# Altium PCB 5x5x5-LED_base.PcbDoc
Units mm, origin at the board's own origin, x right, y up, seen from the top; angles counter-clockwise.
Board outline 97.2 x 97.2 mm, 2 copper layers (Top Layer, Bottom Layer); 46 components, 49 nets, 151 pads, 28 vias.
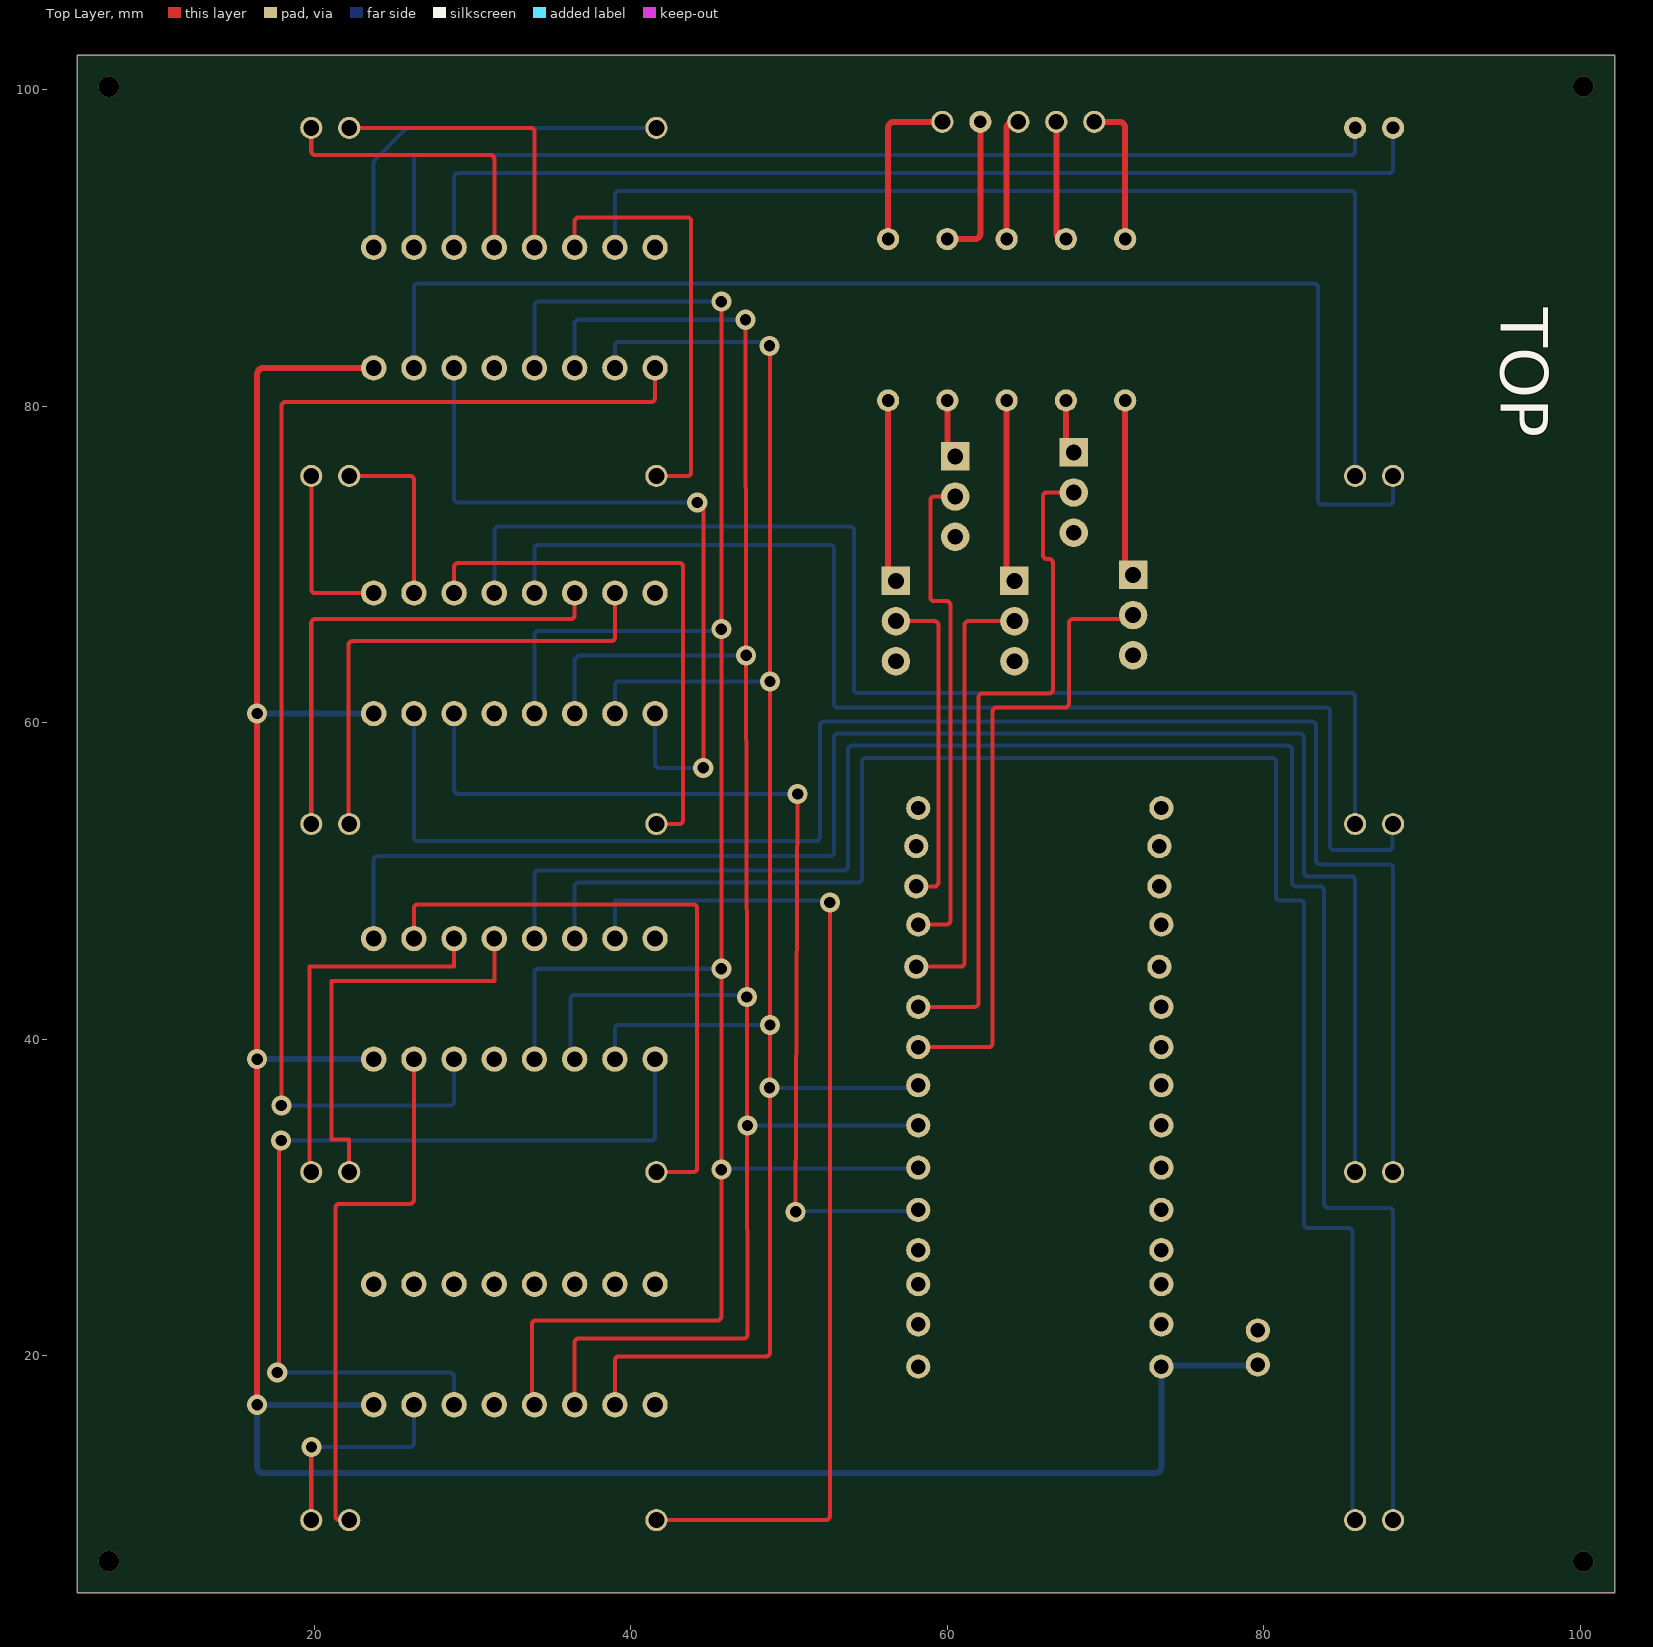
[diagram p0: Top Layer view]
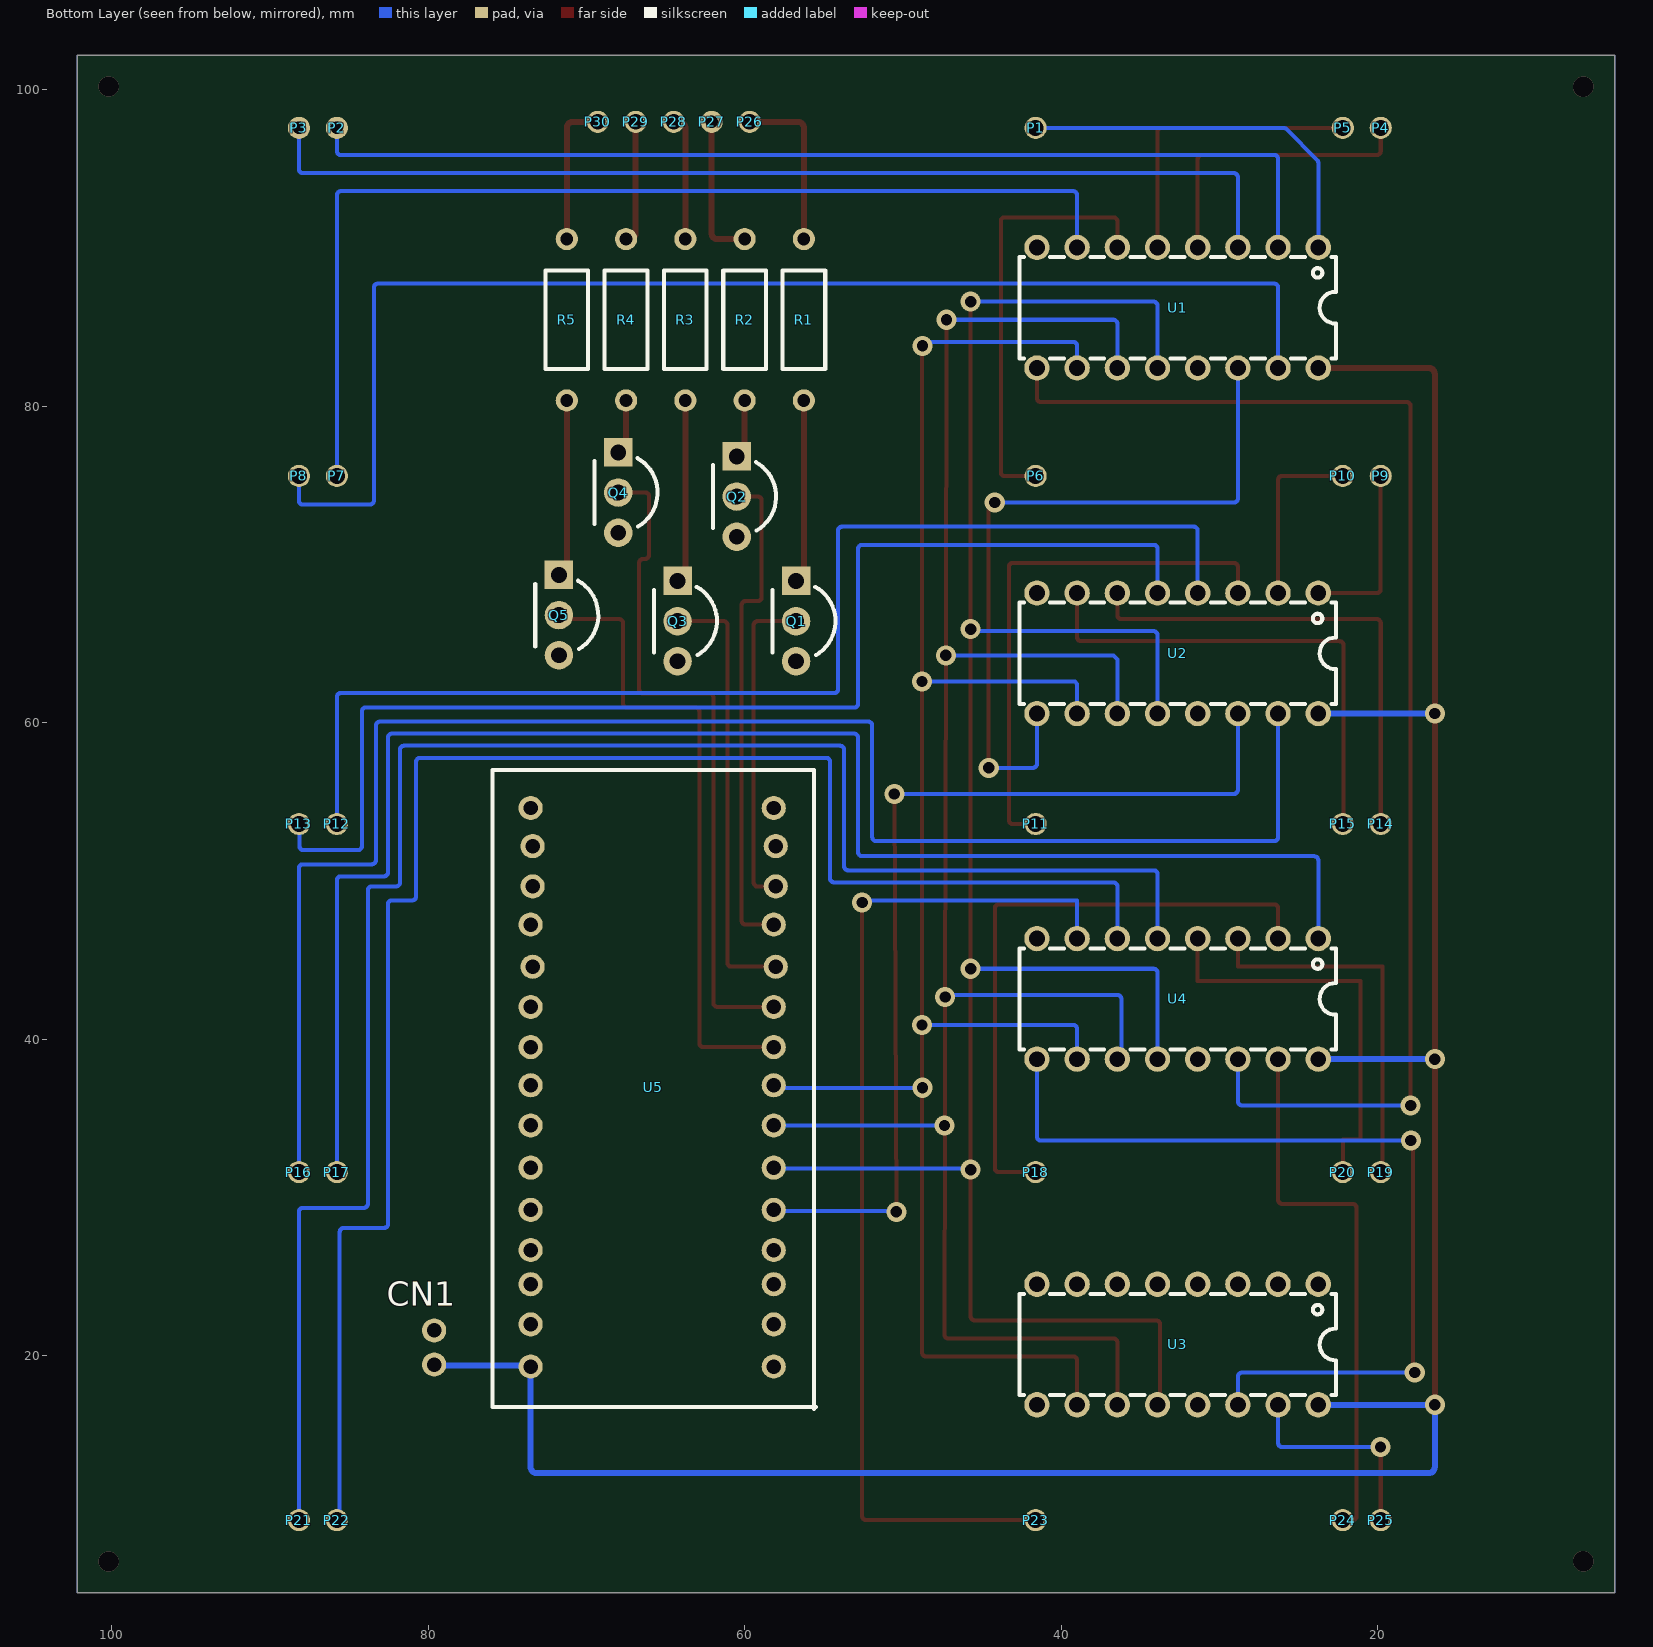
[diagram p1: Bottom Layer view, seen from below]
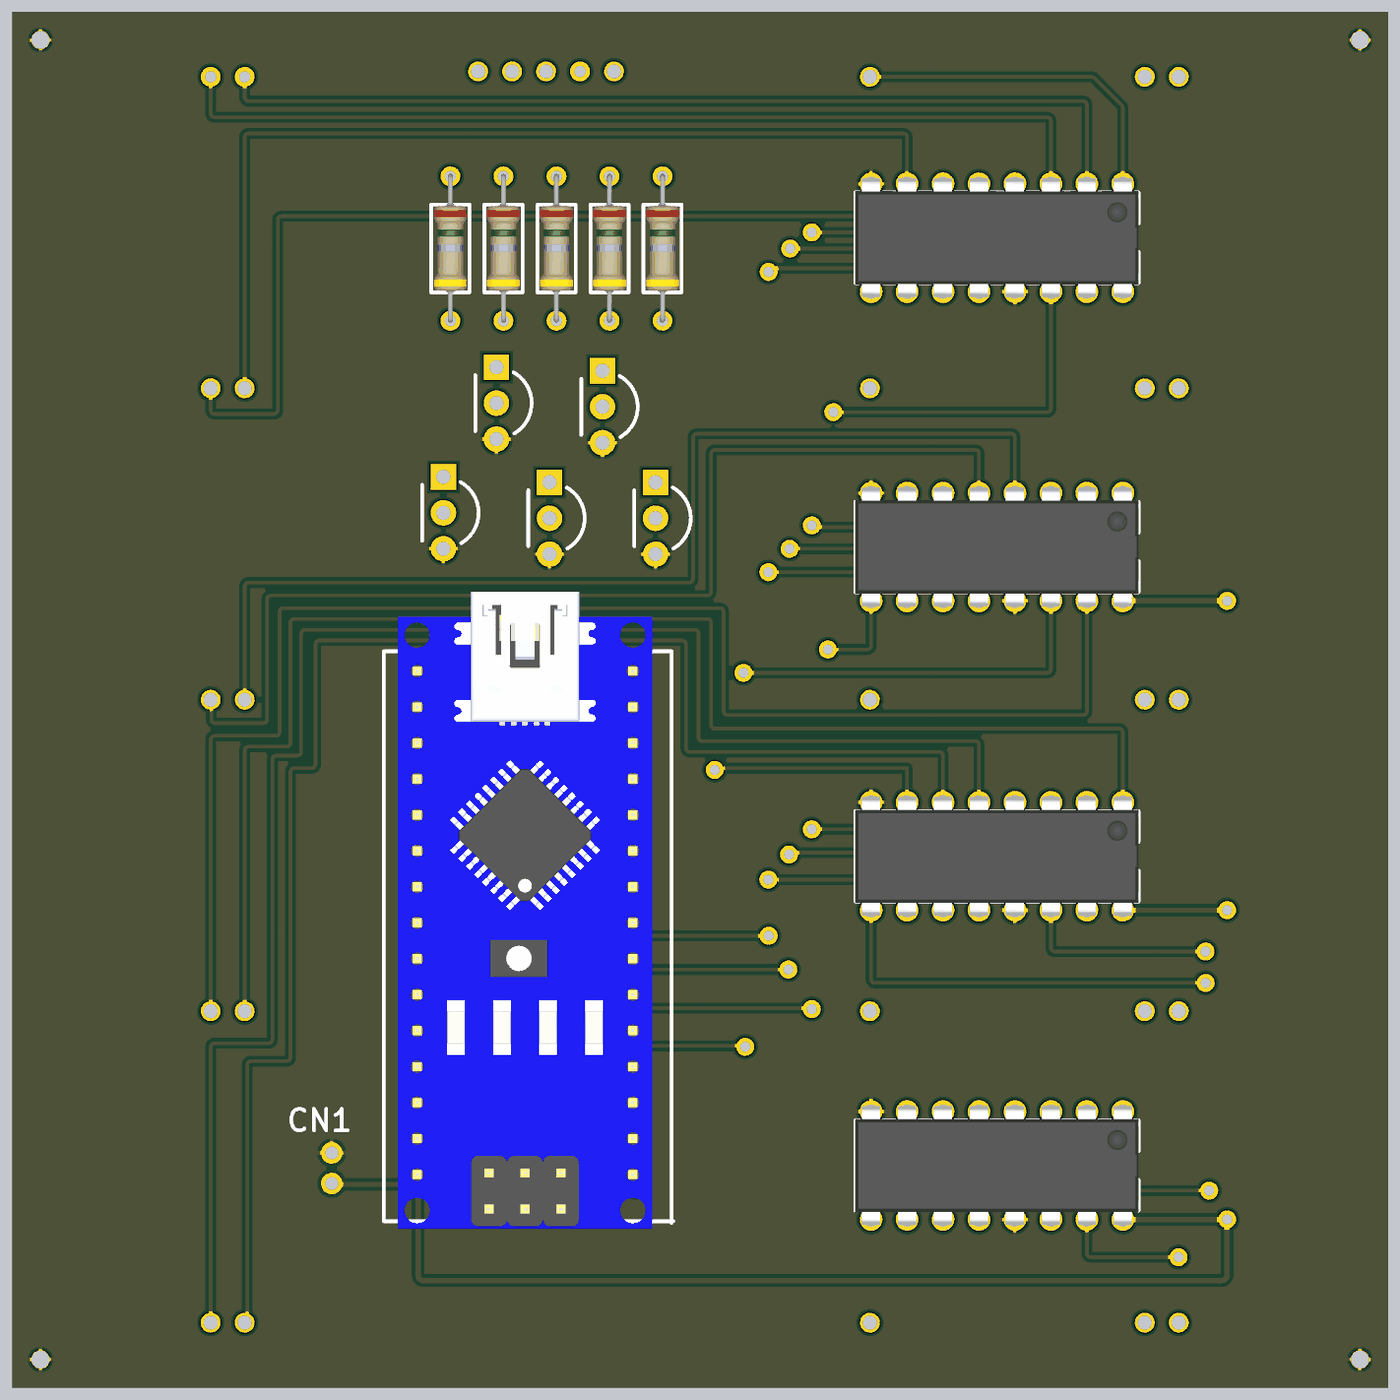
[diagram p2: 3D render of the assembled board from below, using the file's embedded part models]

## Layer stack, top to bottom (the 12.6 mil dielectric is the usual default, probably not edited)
Top Solder: solder mask 0.0102, Solder Resist, Dk 3.5
Top Layer: signal copper 0.0356
Dielectric 1: dielectric 0.32, FR-4, Dk 4.8
Bottom Layer: signal copper 0.0356
Bottom Solder: solder mask 0.0102, Solder Resist, Dk 3.5

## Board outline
5,5 102.198,5 102.198,102.198 5,102.198

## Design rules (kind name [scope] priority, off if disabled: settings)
Clearance [All] p1: gap=0.254 ignorepadtopadclearanceinfootprint=FALSE
PolygonConnect [All] p1: connectstyle=Relief reliefconductorwidth=0.254 reliefentries=4 polygonreliefangle="90 Angle" airgapwidth=0.254
RoutingVias [All] p1: holewidth=0.711 width=1.27 viastyle="Through Hole" minholewidth=0.711 minwidth=1.27 maxholewidth=0.711 maxwidth=1.27
SolderMaskExpansion [All] p1: expansion=0.102 istentingtop=FALSE
SupplyNets "Schematic Supply Nets_1" [InNet('GND')] p1: voltage=0.000
SupplyNets "Schematic Supply Nets" [InNet('+5')] p2: voltage=0.000
Width [All] p1: maxlimit=3 minlimit=0.254 preferedwidth=0.254 minimp=50.000000 maximp=50.000000 favimp=50.000000
30 further rules are at their usual default settings.

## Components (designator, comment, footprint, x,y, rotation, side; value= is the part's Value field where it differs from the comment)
CN1 "Power Connector" "POWER PORT" 79.629,19.431 r0 bottom
P1 "Port_1" port#1 41.613,93.599 r180 bottom
P2 "Port_1" port#2 85.777,93.599 r180 bottom
P3 "Port_1" port#2 88.177,93.599 r180 bottom
P4 "Port_1" port#1 19.799,93.599 r180 bottom
P5 "Port_1" port#1 22.199,93.599 r180 bottom
P6 "Port_1" port#3 41.613,72.599 r180 bottom
P7 "Port_1" port#3 85.777,72.599 r180 bottom
P8 "Port_1" port#3 88.177,72.599 r180 bottom
P9 "Port_1" port#3 19.799,72.599 r180 bottom
P10 "Port_1" port#4 22.2,72.599 r90 bottom
P11 "Port_1" port#5 41.613,51.599 r180 bottom
P12 "Port_1" port#6 85.778,51.599 r90 bottom
P13 "Port_1" port#6 88.178,51.599 r90 bottom
P14 "Port_1" port#6 19.8,51.599 r90 bottom
P15 "Port_1" port#6 22.2,51.599 r90 bottom
P16 "Port_1" port#7 88.178,30.599 r90 bottom
P17 "Port_1" port#7 85.778,30.599 r90 bottom
P18 "Port_1" port#7 41.614,30.599 r90 bottom
P19 "Port_1" port#7 19.8,30.599 r90 bottom
P20 "Port_1" port#7 22.2,30.599 r90 bottom
P21 "Port_1" port#8 88.177,9.599 r180 bottom
P22 "Port_1" port#8 85.778,9.599 r90 bottom
P23 "Port_1" port#8 41.614,9.599 r90 bottom
P24 "Port_1" port#8 22.2,9.599 r90 bottom
P25 "Port_1" port#8 19.8,9.599 r90 bottom
P26 "Port_1" port#9 59.69,93.98 r90 bottom locked
P27 "Port_1" port#10 62.09,93.98 r90 bottom locked
P28 "Port_1" port#9 64.49,93.98 r90 bottom locked
P29 "Port_1" port#9 66.89,93.98 r90 bottom locked
P30 "Port_1" port#9 69.29,93.98 r90 bottom locked
Q1 "BC547BTA" TO-92-3_L4.8-W3.7-P2.54-L 56.754,66.421 r270 bottom locked
Q2 "BC547BTA" TO-92-3_L4.8-W3.7-P2.54-L 60.501,74.295 r270 bottom locked
Q3 "BC547BTA" TO-92-3_L4.8-W3.7-P2.54-L 64.247,66.421 r270 bottom locked
Q4 "BC547BTA" TO-92-3_L4.8-W3.7-P2.54-L 67.994,74.549 r270 bottom locked
Q5 "BC547BTA" TO-92-3_L4.8-W3.7-P2.54-L 71.74,66.802 r270 bottom locked
R1 "1kΩ" RES-TH_BD2.7-L6.2-P10.20-D0.4 56.261,85.471 r270 bottom locked
R2 "1kΩ" RES-TH_BD2.7-L6.2-P10.20-D0.4 60.008,85.471 r270 bottom locked
R3 "1kΩ" RES-TH_BD2.7-L6.2-P10.20-D0.4 63.754,85.471 r270 bottom locked
R4 "1kΩ" RES-TH_BD2.7-L6.2-P10.20-D0.4 67.501,85.471 r270 bottom locked
R5 "1kΩ" RES-TH_BD2.7-L6.2-P10.20-D0.4 71.247,85.471 r270 bottom locked
U1 "74HC595N" DIP-16_L20.0-W6.4-P2.54-LS7.6-BL 32.639,86.233 r0 bottom locked
U2 "74HC595N" DIP-16_L20.0-W6.4-P2.54-LS7.6-BL 32.639,64.389 r0 bottom locked
U3 "74HC595N" DIP-16_L20.0-W6.4-P2.54-LS7.6-BL 32.639,20.701 r0 bottom locked
U4 "74HC595N" DIP-16_L20.0-W6.4-P2.54-LS7.6-BL 32.639,42.545 r0 bottom locked
U5 "ARDUINO_NANO" "ARDUINO NANO." 65.722,36.83 r0 bottom locked

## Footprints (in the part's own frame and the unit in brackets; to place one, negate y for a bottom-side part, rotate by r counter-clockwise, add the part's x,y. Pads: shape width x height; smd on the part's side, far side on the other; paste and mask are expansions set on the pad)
"ARDUINO NANO." [mil]
  round 60 hole 36 paste-99999 mask+2: 1(-297.5,690) 2(-297.5,585) 3(-297.5,485) 4(-297.5,400) 5(-297.5,300) 6(-297.5,195) 7(-297.5,90) 8(-297.5,-10) 9(-297.5,-105) 10(-297.5,-205) 11(-302.5,-305) 12(-297.5,-410) 13(-302.5,-505) 14(-302.5,-605) 15(-297.5,-700) 16(307.5,-700) 17(302.5,-605) 18(302.5,-505) 19(307.5,-410) 20(302.5,-305) 21(307.5,-205) 22(307.5,-105) 23(307.5,-10) 24(307.5,90) 25(307.5,195) 26(307.5,300) 27(307.5,400) 28(307.5,485) 29(307.5,585) 30(307.5,690)
  silkscreen extent -402,-795 402,795, body extent -344,-961 364,810, height 646
DIP-16_L20.0-W6.4-P2.54-LS7.6-BL [mm]
  round 1.6 hole 1: 1(-8.89,-3.81) 2(-6.35,-3.81) 3(-3.81,-3.81) 4(-1.27,-3.81) 5(1.27,-3.81) 6(3.81,-3.81) 7(6.35,-3.81) 8(8.89,-3.81) 9(8.89,3.81) 10(6.35,3.81) 11(3.81,3.81) 12(1.27,3.81) 13(-1.27,3.81) 14(-3.81,3.81) 15(-6.35,3.81) 16(-8.89,3.81)
  silkscreen extent -10,-3.2 10,3.2, body extent -10.02,-4.57 10.02,4.57, height 4.14
port#1 [mm]
  round 1.4 hole 1 copper offset 0,0: 1(0,4)
port#2 [mm]
  round 1.4 hole 0.8 copper offset 0,0: 1(0,4)
port#3 [mm]
  round 1.4 hole 1 copper offset 0,0: 1(0,3)
port#4 [mm]
  round 1.4 hole 1 copper offset 0,0: 1(3,0)
port#5 [mm]
  round 1.4 hole 1 copper offset 0,0: 1(0,2)
port#6 [mm]
  round 1.4 hole 1 copper offset 0,0: 1(2,0)
port#7 [mm]
  round 1.4 hole 1 copper offset 0,0: 1(1,0)
port#8 [mm]
  round 1.4 hole 1 copper offset 0,0: 1(0,0)
port#9 [mm]
  round 1.4 hole 1 copper offset 0,0: 1(4,0)
port#10 [mm]
  round 1.4 hole 0.8 copper offset 0,0: 1(4,0)
"POWER PORT" [mil]
  round 60 hole 36 paste-99999 mask+2: 1(0,0) 2(0,-85)
RES-TH_BD2.7-L6.2-P10.20-D0.4 [mm]
  round 1.4 hole 0.8 copper offset 0,0: 1(-5.1,0) 2(5.1,0)
  silkscreen extent -3.1,-1.35 3.1,1.35, body extent -5.27,-1.15 5.24,1.15, height 2.51
TO-92-3_L4.8-W3.7-P2.54-L [mm]
  rect 1.8x1.8 hole 1: 1(-2.54,0)
  round 1.8 hole 1: 2(0,0) 3(2.54,0)
  silkscreen extent -2.17,-1.5 2.14,2.48

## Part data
Q1 Q2 Q3 Q4 Q5: Collector Cut-Off Current (Icbo)=15nA, Collector-Emitter Saturation Voltage (VCE(sat)@Ic,Ib)=90mV@10mA,0.5mA, DC Current Gain (hFE@Ic,Vce)=110@2mA,5V, JLCPCB Part Class="Extended Part", LCSC Part Name="NPN 电流:100mA 耐压:45V", Manufacturer=onsemi(安森美), Operating Temperature=-65℃~+150℃, Transition Frequency (fT)=300MHz
R1 R2 R3 R4 R5: library part MF1/4W-1K±1%-ST52, JLCPCB Part Class="Extended Part", LCSC Part Name="金属膜电阻 1kΩ ±1% 250mW", Manufacturer=VO(翔胜), Operating Temperature Range=-55℃~+155℃, Overload Voltage (Max)=250V, Power(Watts)=250mW, Temperature Coefficient=±100ppm/℃, Tolerance=±1%
U1 U2 U3 U4: library part 74HC595N_C507175, JLCPCB Part Class="Extended Part", LCSC Part Name="具有三态输出寄存器的 8 位移位寄存器", Manufacturer=HGSEMI(华冠)

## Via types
v1: diameter 1.27, hole 0.711, Top Layer to Bottom Layer, 24 vias
v2: diameter 1.27, hole 1.27, Top Layer to Bottom Layer, 4 vias

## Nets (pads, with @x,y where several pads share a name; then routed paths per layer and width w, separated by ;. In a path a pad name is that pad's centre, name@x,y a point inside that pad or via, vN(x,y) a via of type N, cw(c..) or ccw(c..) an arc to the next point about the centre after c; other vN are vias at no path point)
+5: CN1.1 U1.16 U2.16 U3.16 U4.16 U5.30 | length 168.8
  Top Layer w0.381: v1(16.383,16.891) v1(16.383,38.735) v1(16.383,60.579) 16.383,82.042 cw(c16.764,82.042) 16.764,82.423 U1.16 ; CN1.1@79.566,19.367 CN1.1
  Bottom Layer w0.381: v1(16.383,38.735) U4.16 ; v1(16.383,60.579) U2.16 ; U3.16 v1(16.383,16.891) 16.383,12.952 ccw(c16.764,12.954) 16.764,12.573 73.152,12.573 ccw(c73.152,12.954) 73.533,12.954 U5.30 ; U5.30@73.596,19.367 CN1.1@79.566,19.367
CLOCK_PIN: U1.12 U2.12 U3.12 U4.12 U5.6 | length 144
  Top Layer w0.254: U3.12 33.829,16.971 cw(c34.009,17.151) 33.755,17.151 33.755,21.971 cw(c34.009,21.971) 34.009,22.225 45.466,22.225 ccw(c45.466,22.479) 45.72,22.479 v1(45.72,31.75) v1(45.72,44.45) v1(45.72,86.614)
  Bottom Layer w0.254: U4.12 33.909,44.196 cw(c34.163,44.196) 34.163,44.45 v1(45.72,44.45) ; U2.12 33.909,65.532 cw(c34.163,65.532) 34.163,65.786 v1@45.488,65.786 ; U1.12 33.909,86.36 cw(c34.163,86.36) 34.163,86.614 v1(45.72,86.614) ; v1(45.72,31.75) 45.783,31.813 58.102,31.813 U5.6
  other v1: 45.72,65.913
Data0: U2.14 U5.5 | length 60.9
  Top Layer w0.254: v1(50.419,29.083) v1(50.546,55.499)
  Bottom Layer w0.254: U2.14 28.829,55.753 ccw(c29.083,55.753) 29.083,55.499 v1(50.546,55.499) ; v1(50.419,29.083) 50.482,29.146 58.102,29.146 U5.5
Data1: U1.14 U2.9 | length 47
  Top Layer w0.254: v1(44.196,73.914) 44.503,73.607 cw(c44.323,73.428) 44.577,73.428 v1(44.577,57.15)
  Bottom Layer w0.254: U1.14 28.829,74.168 ccw(c29.083,74.168) 29.083,73.914 v1(44.196,73.914) ; U2.9 41.529,57.409 ccw(c41.783,57.409) 41.603,57.229 41.608,57.224 ccw(c41.788,57.404) 41.788,57.15 v1(44.577,57.15)
Data2: U1.9 U4.14 | length 83.7
  Top Layer w0.254: v1(17.907,35.814) 17.907,80.01 cw(c18.161,80.01) 18.161,80.264 41.222,80.264 ccw(c41.222,80.698) 41.351,80.284 ccw(c41.275,80.526) 41.529,80.525 U1.9
  Bottom Layer w0.254: v1(17.907,35.814) 28.575,35.814 ccw(c28.575,36.068) 28.829,36.068 U4.14
Data3: U3.14 U4.9 | length 56.5
  Top Layer w0.254: v1(17.653,18.923) 17.774,19.044 17.774,33.472 v1(17.896,33.594)
  Bottom Layer w0.254: v1(17.653,18.923) 28.575,18.923 cw(c28.575,18.669) 28.829,18.669 U3.14 ; v1(17.896,33.594) 41.275,33.594 ccw(c41.275,33.848) 41.529,33.848 U4.9
GND: CN1.2 Q1.3 Q2.3 Q3.3 Q4.3 Q5.3 U1.8 U1.13 U2.8 U2.13 U3.8 U3.13 U4.8 U4.13 U5.4 U5.29
  other v2: 100.2,6.994 7,7 6.999,100.198 100.198,100.202
LATCH_PIN: U1.11 U2.11 U3.11 U4.11 U5.7 | length 133.4
  Top Layer w0.254: U3.11 36.449,20.828 cw(c36.703,20.828) 36.703,21.082 47.118,21.082 ccw(c47.118,21.336) 47.372,21.336 v1@47.346,34.544 ; v1(47.244,85.471) v1(47.287,64.262) 47.33,42.799 v1(47.33,42.672) 47.35,42.651 47.35,34.565 v1(47.371,34.544)
  Bottom Layer w0.254: U4.11 36.269,38.915 cw(c36.449,39.094) 36.195,39.094 36.195,42.545 cw(c36.449,42.545) 36.449,42.799 47.203,42.799 v1(47.33,42.672) ; U2.11 36.449,64.008 36.703,64.262 v1(47.287,64.262) ; U1.11 36.449,85.217 cw(c36.703,85.217) 36.703,85.471 v1(47.244,85.471) ; v1(47.371,34.544) U5.7
Layer_0: Q1.2 U5.13 | length 20.6
  Top Layer w0.254: Q1.2 59.182,66.421 cw(c59.182,66.167) 59.436,66.167 59.436,49.911 cw(c59.182,49.911) 59.362,49.731 59.287,49.657 U5.13
Layer_1: Q2.2 U5.12 | length 31.5
  Top Layer w0.254: U5.12 59.944,47.244 ccw(c59.944,47.498) 60.198,47.498 60.198,67.437 ccw(c59.944,67.437) 59.944,67.691 59.182,67.691 cw(c59.182,67.945) 58.928,67.945 58.928,74.041 cw(c59.182,74.041) 59.182,74.295 Q2.2
Layer_2: Q3.2 U5.11 | length 27.8
  Top Layer w0.254: U5.11 60.833,44.577 ccw(c60.833,44.831) 61.087,44.831 61.087,66.167 cw(c61.341,66.167) 61.341,66.421 Q3.2
Layer_3: Q4.2 U5.10 | length 43
  Top Layer w0.254: U5.10 61.722,42.037 ccw(c61.722,42.291) 61.976,42.291 61.976,61.596 cw(c62.23,61.595) 62.23,61.849 66.421,61.849 ccw(c66.421,62.103) 66.675,62.103 66.675,70.104 ccw(c66.421,70.104) 66.421,70.358 66.294,70.358 cw(c66.294,70.612) 66.04,70.612 66.04,74.295 cw(c66.294,74.295) 66.294,74.549 Q4.2
Layer_4: Q5.2 U5.9 | length 40.3
  Top Layer w0.254: U5.9 62.611,39.497 ccw(c62.611,39.751) 62.865,39.751 62.865,60.706 cw(c63.119,60.706) 63.119,60.96 67.437,60.96 ccw(c67.437,61.214) 67.691,61.214 67.691,66.296 cw(c67.945,66.294) 67.945,66.548 71.486,66.548 Q5.2
NetP1_1: P1.1 U1.1 | length 24.2
  Bottom Layer w0.254: U1.1 23.749,95.399 cw(c24.003,95.399) 23.823,95.578 25.77,97.525 cw(c25.949,97.345) 25.949,97.599 P1.1
NetP2_1: P2.1 U1.2 | length 66.8
  Bottom Layer w0.254: U1.2 26.289,95.631 cw(c26.543,95.631) 26.543,95.885 85.523,95.885 ccw(c85.523,96.139) 85.777,96.139 P2.1
NetP3_1: P3.1 U1.3 | length 66.7
  Bottom Layer w0.254: U1.3 28.829,94.488 cw(c29.083,94.488) 29.083,94.742 87.924,94.742 ccw(c87.924,94.996) 88.178,94.996 P3.1
NetP4_1: P4.1 U1.4 | length 18.9
  Top Layer w0.254: P4.1 19.799,96.139 ccw(c20.053,96.139) 20.053,95.885 31.115,95.885 cw(c31.115,95.631) 31.369,95.631 U1.4
NetP5_1: P5.1 U1.5 | length 19.2
  Top Layer w0.254: P5.1 33.655,97.599 cw(c33.655,97.345) 33.909,97.345 U1.5
NetP6_1: P6.1 U1.6 | length 27.5
  Top Layer w0.254: U1.6 36.449,91.694 cw(c36.703,91.694) 36.703,91.948 43.561,91.948 cw(c43.561,91.694) 43.815,91.694 43.815,75.84 cw(c43.561,75.84) 43.561,75.586 P6.1@41.627,75.586
NetP7_1: P7.1 U1.7 | length 68.1
  Bottom Layer w0.254: U1.7 38.989,93.345 cw(c39.243,93.345) 39.243,93.599 85.524,93.599 cw(c85.524,93.345) 85.778,93.345 P7.1
NetP8_1: P8.1 U1.15 | length 82.6
  Bottom Layer w0.254: U1.15 26.289,87.608 26.363,87.683 cw(c26.543,87.503) 26.543,87.757 83.185,87.757 cw(c83.185,87.503) 83.439,87.503 83.439,74.041 ccw(c83.693,74.041) 83.693,73.787 87.924,73.787 ccw(c87.924,74.041) 88.178,74.041 P8.1
NetP9_1: P9.1 U2.1 | length 11.2
  Top Layer w0.254: P9.1@19.802,75.595 19.802,68.453 ccw(c20.056,68.453) 20.056,68.199 U2.1
NetP10_1: P10.1 U2.2 | length 11.4
  Top Layer w0.254: P10.1 26.035,75.599 cw(c26.035,75.345) 26.289,75.345 U2.2
NetP11_1: P11.1 U2.3 | length 34.3
  Top Layer w0.254: U2.3 28.829,69.85 cw(c29.083,69.85) 29.083,70.104 43.053,70.104 cw(c43.053,69.85) 43.307,69.85 43.307,53.853 cw(c43.053,53.853) 43.053,53.599 P11.1
NetP12_1: P12.1 U2.4 | length 77
  Bottom Layer w0.254: U2.4 31.369,72.136 cw(c31.623,72.136) 31.623,72.39 53.848,72.39 cw(c53.848,72.136) 54.102,72.136 54.102,62.129 ccw(c54.356,62.129) 54.356,61.875 85.524,61.875 cw(c85.524,61.621) 85.778,61.621 P12.1
NetP13_1: P13.1 U2.5 | length 77.6
  Bottom Layer w0.254: U2.5 33.909,70.993 cw(c34.163,70.993) 34.163,71.247 52.578,71.247 cw(c52.578,70.993) 52.832,70.993 52.832,61.214 ccw(c53.086,61.214) 53.086,60.96 83.947,60.96 cw(c83.947,60.706) 84.201,60.706 84.201,52.197 ccw(c84.455,52.197) 84.455,51.943 87.884,51.943 ccw(c87.884,52.197) 88.138,52.197 88.138,53.559 P13.1
NetP14_1: P14.1 U2.6 | length 31
  Top Layer w0.254: P14.1 19.8,66.294 cw(c20.054,66.294) 20.054,66.548 36.195,66.548 ccw(c36.195,66.802) 36.449,66.802 U2.6
NetP15_1: P15.1 U2.7 | length 31.2
  Top Layer w0.254: P15.1 22.194,53.606 cw(c22.402,53.753) 22.148,53.753 22.148,64.897 cw(c22.402,64.897) 22.402,65.151 38.735,65.151 ccw(c38.735,65.405) 38.989,65.405 U2.7
NetP16_1: P16.1 U2.15 | length 105.3
  Bottom Layer w0.254: U2.15 26.289,52.772 ccw(c26.543,52.772) 26.543,52.518 51.689,52.518 ccw(c51.689,52.772) 51.943,52.772 51.943,59.818 cw(c52.197,59.817) 52.197,60.071 83.058,60.071 cw(c83.058,59.817) 83.312,59.817 83.312,51.308 ccw(c83.566,51.308) 83.566,51.054 87.921,51.054 cw(c87.921,50.8) 88.175,50.8 P16.1@88.175,31.604
NetP17_1: P17.1 U4.1 | length 102
  Bottom Layer w0.254: U4.1 23.749,51.309 cw(c24.003,51.308) 24.003,51.562 52.578,51.562 ccw(c52.578,51.816) 52.832,51.816 52.832,59.055 cw(c53.086,59.055) 53.086,59.309 82.296,59.309 cw(c82.296,59.055) 82.55,59.055 82.55,50.546 ccw(c82.804,50.546) 82.804,50.292 85.524,50.292 cw(c85.524,50.038) 85.778,50.038 P17.1
NetP18_1: P18.1 U4.2 | length 39.2
  Top Layer w0.254: U4.2 26.289,48.26 cw(c26.543,48.26) 26.543,48.514 43.942,48.514 cw(c43.942,48.26) 44.196,48.26 44.196,31.853 cw(c43.942,31.853) 43.942,31.599 P18.1
NetP19_1: P19.1 U4.3 | length 24
  Top Layer w0.254: P19.1 19.685,31.599 19.685,44.577 28.829,44.577 U4.3
NetP20_1: P20.1 U4.4 | length 26.2
  Top Layer w0.254: P20.1 22.2,33.655 21.082,33.655 21.082,43.688 31.369,43.688 U4.4
NetP21_1: P21.1 U4.5 | length 114.5
  Bottom Layer w0.254: U4.5 33.909,50.419 cw(c34.163,50.419) 34.163,50.673 53.467,50.673 ccw(c53.467,50.927) 53.721,50.927 53.721,58.293 cw(c53.975,58.293) 53.975,58.547 81.534,58.547 cw(c81.534,58.293) 81.788,58.293 81.788,49.909 ccw(c82.042,49.911) 82.042,49.657 83.566,49.657 cw(c83.566,49.403) 83.82,49.403 83.82,29.591 ccw(c84.074,29.591) 84.074,29.337 87.923,29.337 cw(c87.923,29.083) 88.177,29.083 P21.1
NetP22_1: P22.1 U4.6 | length 108
  Bottom Layer w0.254: U4.6 36.449,49.657 cw(c36.703,49.657) 36.703,49.911 54.356,49.911 ccw(c54.356,50.165) 54.61,50.165 54.61,57.531 cw(c54.864,57.531) 54.864,57.785 80.518,57.785 cw(c80.518,57.531) 80.772,57.531 80.772,49.022 ccw(c81.026,49.022) 81.026,48.768 82.296,48.768 cw(c82.296,48.514) 82.55,48.514 82.55,28.321 ccw(c82.804,28.321) 82.804,28.067 85.344,28.067 cw(c85.344,27.813) 85.598,27.813 85.598,9.884 ccw(c85.852,9.884) 85.672,9.704 P22.1
NetP23_1: P23.1 U4.7 | length 66
  Top Layer w0.254: P23.1 52.324,9.599 ccw(c52.324,9.853) 52.578,9.853 v1(52.578,48.641)
  Bottom Layer w0.254: U4.7 38.989,48.768 52.578,48.768 v1(52.578,48.641)
NetP24_1: P24.1 U4.15 | length 34.6
  Top Layer w0.254: P24.1 21.59,9.599 cw(c21.59,9.853) 21.336,9.853 21.336,29.337 cw(c21.59,29.337) 21.59,29.591 26.035,29.591 ccw(c26.035,29.845) 26.289,29.845 U4.15
NetP25_1: P25.1 U3.15 | length 13.7
  Top Layer w0.254: P25.1 19.8,14.224 v1(19.812,14.224)
  Bottom Layer w0.254: v1(19.812,14.224) 26.035,14.224 ccw(c26.035,14.478) 26.289,14.478 U3.15
NetP26_1: P26.1 R1.1 | length 10.7
  Top Layer w0.381: R1.1 56.261,97.599 cw(c56.642,97.599) 56.642,97.98 P26.1
NetP27_1: P27.1 R2.1 | length 9.3
  Top Layer w0.381: R2.1 61.72,90.571 ccw(c61.72,90.952) 62.101,90.952 P27.1@62.101,97.969
NetP28_1: P28.1 R3.1 | length 8
  Top Layer w0.381: R3.1 63.754,97.599 cw(c64.135,97.599) 64.135,97.98 P28.1
NetP29_1: P29.1 R4.1 | length 7.9
  Top Layer w0.381: P29.1 66.89,90.952 ccw(c67.271,90.952) 67.271,90.571 R4.1
NetP30_1: P30.1 R5.1 | length 9.2
  Top Layer w0.381: P30.1 70.866,97.98 cw(c70.866,97.599) 71.247,97.599 R5.1
NetQ1_1: Q1.1 R1.2 | length 11.6
  Top Layer w0.381: R1.2 56.261,69.454 Q1.1
NetQ2_1: Q2.1 R2.2 | length 3.7
  Top Layer w0.381: R2.2 60.008,77.328 Q2.1
NetQ3_1: Q3.1 R3.2 | length 11.6
  Top Layer w0.381: R3.2 63.754,69.454 Q3.1
NetQ4_1: Q4.1 R4.2 | length 3.5
  Top Layer w0.381: R4.2 67.501,77.582 Q4.1
NetQ5_1: Q5.1 R5.2 | length 11.2
  Top Layer w0.381: R5.2 71.247,69.835 Q5.1
RESET: U1.10 U2.10 U3.10 U4.10 U5.8 | length 121
  Top Layer w0.254: U3.10 38.989,19.685 cw(c39.243,19.685) 39.243,19.939 48.536,19.939 ccw(c48.536,20.193) 48.79,20.193 v1(48.79,40.894) v1(48.79,62.611) 48.79,82.677 ccw(c48.536,82.677) 48.79,82.682 v1(48.768,83.82)
  Bottom Layer w0.254: U4.10 38.989,40.64 cw(c39.243,40.64) 39.243,40.894 v1(48.79,40.894) ; U2.10 38.989,62.462 39.138,62.611 v1(48.79,62.611) ; U1.10 38.989,83.82 cw(c39.243,83.82) 39.243,84.074 48.409,84.074 cw(c48.409,83.82) 48.588,84 v1(48.768,83.82) ; v1(48.768,36.927) 57.904,36.927 ccw(c57.904,37.181) 58.083,37.001 U5.8
pads on no net: U3.1 U3.2 U3.3 U3.4 U3.5 U3.6 U3.7 U3.9 U5.1 U5.2 U5.3 U5.14 U5.15 U5.16 U5.17 U5.18 U5.19 U5.20 U5.21 U5.22 U5.23 U5.24 U5.25 U5.26 U5.27 U5.28

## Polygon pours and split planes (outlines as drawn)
GND on Top Layer "NONET_L01_P000" (solid, shelved, pour order 0): 5,5 102.198,5 102.198,102.198 5,102.198
GND on Bottom Layer "NONET_L02_P001" (solid, shelved, pour order 1): 5,5 102.198,5 102.198,102.198 5,102.198

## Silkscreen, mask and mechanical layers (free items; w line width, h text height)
Top Overlay:
  text "TOP" at 94.996,86.233 h3 r270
